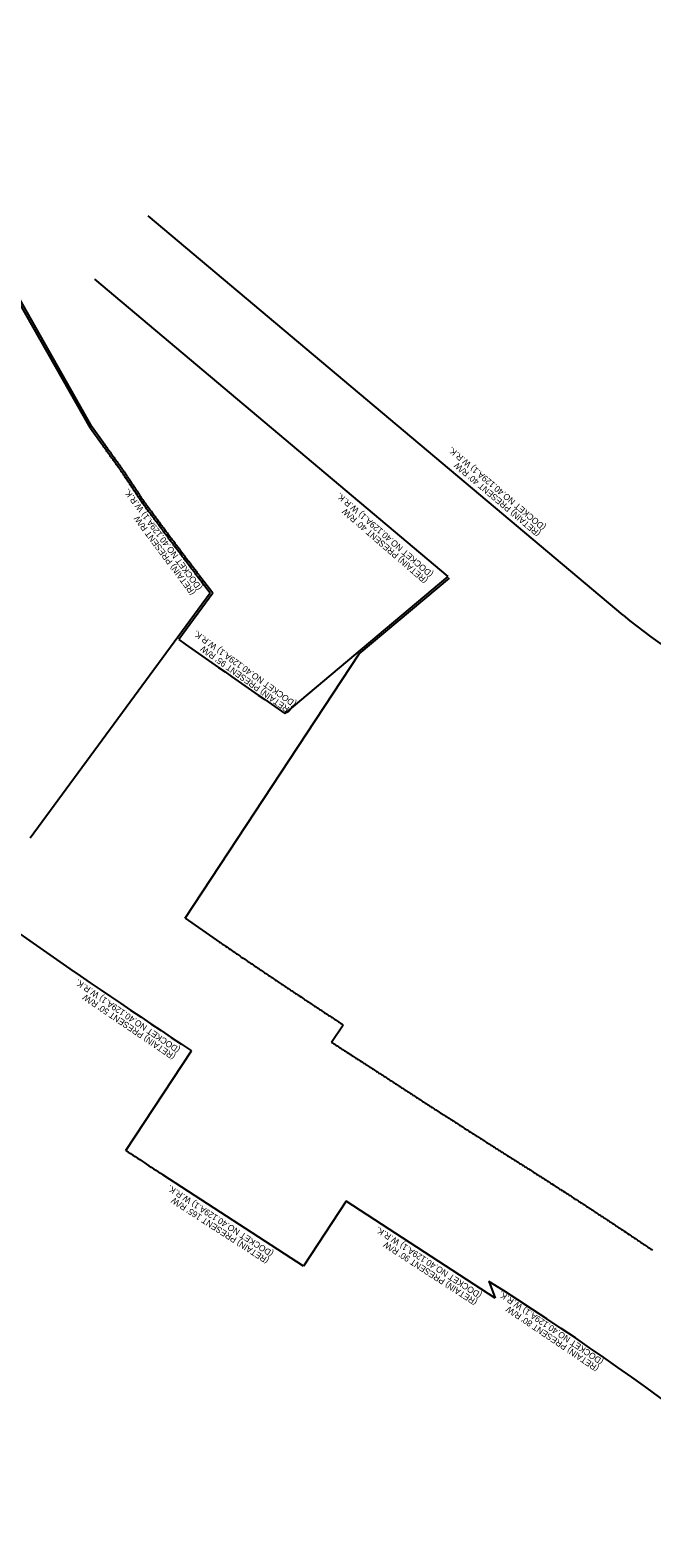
# Model space of a CAD drawing. Extents: x 2004008 to 2024436, y 806921 to 864820.
# Drawn here: x 2021261 to 2021860, y 814347 to 815799 of the extents above; entities that cross this region are included whole.
import ezdxf

# ---------------------------------------------------------------- set-up
doc = ezdxf.new("R2010")
doc.units = 0
for name, color, linetype in [('RD_PD_DR_ErosCtrl', 7, 'Continuous'), ('RD_PD_Final_LnLine', 7, 'Continuous'), ('RD_PD_MedBWall', 7, 'Continuous')]:
    doc.layers.add(name, color=color, linetype=linetype)

msp = doc.modelspace()

# ---------------------------------------------------------------- linework, layer by layer
at = {"layer": 'RD_PD_Final_LnLine'}
for p, q in [((2021832.3, 815235.7), (2021374.9, 815620.3)), ((2021663.8, 815272.9), (2021323.4, 815559.1)), ((2021506.7, 815141.1), (2021663.8, 815272.9)), ((2021437, 815257), (2021404.3, 815212.4)), ((2021353.4, 814720.1), (2021416.7, 814816.1)), ((2021524.6, 814608.7), (2021388.9, 814696.9)), ((2021565.5, 814671.5), (2021524.6, 814608.7)), ((2021709.1, 814578.1), (2021565.5, 814671.5)), ((2021703.1, 814594.2), (2021709.1, 814578.1))]:
    msp.add_line(p, q, dxfattribs=at)
for points in [[(2021321, 815416.6), (2021245.8, 815549.5), (2021197.2, 815663), (2021170, 815798.8)], [(2021437, 815257), (2021428.6, 815268), (2021428.1, 815268.7), (2021427.5, 815269.5), (2021426.8, 815270.4), (2021426.3, 815271.1), (2021425.7, 815271.9), (2021425.1, 815272.7), (2021424.5, 815273.5), (2021423.4, 815274.8), (2021423.3, 815275), (2021423.2, 815275.2), (2021422.5, 815276.1), (2021421.9, 815276.9), (2021421.3, 815277.6), (2021420.7, 815278.5), (2021420.1, 815279.3), (2021419.5, 815280.1), (2021418.9, 815280.9), (2021418.3, 815281.6), (2021417.7, 815282.5), (2021417, 815283.3), (2021416.5, 815284), (2021415.9, 815284.8), (2021415.2, 815285.7), (2021414.7, 815286.4), (2021414.1, 815287.2), (2021413.4, 815288.1), (2021412.8, 815288.8), (2021412.3, 815289.6), (2021411.6, 815290.4), (2021411, 815291.2), (2021410.4, 815292), (2021409.8, 815292.8), (2021409.3, 815293.5), (2021408.6, 815294.4), (2021408, 815295.2), (2021407.5, 815295.9), (2021406.8, 815296.8), (2021406.2, 815297.6), (2021405.6, 815298.3), (2021405, 815299.2), (2021404.4, 815300), (2021403.8, 815300.8), (2021403.2, 815301.6), (2021402.6, 815302.3), (2021402, 815303.2), (2021401.3, 815304.1), (2021400.8, 815304.7), (2021400.2, 815305.5), (2021399.5, 815306.5), (2021399, 815307.2), (2021398.4, 815307.9), (2021397.7, 815308.8), (2021397.2, 815309.6), (2021396.5, 815310.4), (2021396, 815311.1), (2021395.4, 815311.9), (2021394.6, 815312.9), (2021394.1, 815313.6), (2021393.5, 815314.5), (2021392.9, 815315.3), (2021392.3, 815316), (2021391.7, 815316.9), (2021391.1, 815317.7), (2021390.5, 815318.4), (2021389.9, 815319.3), (2021389.3, 815320.1), (2021388.7, 815320.9), (2021388.1, 815321.7), (2021387.5, 815322.5), (2021387, 815323.3), (2021386.3, 815324.1), (2021385.8, 815324.9), (2021385.2, 815325.7), (2021384.5, 815326.5), (2021383.9, 815327.4), (2021383.4, 815328.1), (2021382.7, 815329), (2021382.1, 815329.8), (2021381.5, 815330.6), (2021381, 815331.4), (2021380.4, 815332.1), (2021379.8, 815333), (2021379.2, 815333.8), (2021378.6, 815334.5), (2021378, 815335.4), (2021377.4, 815336.2), (2021376.9, 815336.8), (2021376.2, 815337.8), (2021375.6, 815338.6), (2021375, 815339.3), (2021374.4, 815340.2), (2021373.8, 815341), (2021373.3, 815341.7), (2021372.6, 815342.6), (2021372, 815343.5), (2021371.4, 815344.3), (2021370.4, 815345.8), (2021369.8, 815346.7), (2021369.2, 815347.5), (2021368.7, 815348.3), (2021368.2, 815349.1), (2021367.6, 815349.9), (2021367, 815350.8), (2021366.5, 815351.7), (2021366, 815352.4), (2021365.4, 815353.3), (2021364.8, 815354.1), (2021364.2, 815355), (2021363.7, 815355.8), (2021363.2, 815356.6), (2021362.6, 815357.4), (2021362.1, 815358.2), (2021361.5, 815359.1), (2021360.9, 815360), (2021360.4, 815360.8), (2021359.9, 815361.6), (2021359.3, 815362.4), (2021358.7, 815363.2), (2021358.1, 815364.1), (2021357.6, 815365), (2021357.1, 815365.7), (2021356.5, 815366.6), (2021356, 815367.4), (2021355.4, 815368.2), (2021354.8, 815369.1), (2021354.3, 815370), (2021353.7, 815370.7), (2021353.2, 815371.6), (2021352.6, 815372.4), (2021352, 815373.3), (2021351.5, 815374.1), (2021351, 815374.9), (2021350.4, 815375.7), (2021349.9, 815376.4), (2021349.7, 815376.8), (2021349.1, 815377.6), (2021348.6, 815378.3), (2021347.9, 815379.2), (2021347.3, 815380), (2021346.7, 815380.8), (2021346.2, 815381.6), (2021345.6, 815382.5), (2021345, 815383.3), (2021344.4, 815384.1), (2021343.8, 815384.9), (2021343.2, 815385.7), (2021342.6, 815386.6), (2021342, 815387.4), (2021341.5, 815388.1), (2021341, 815388.8), (2021340.3, 815389.8), (2021339.7, 815390.6), (2021339.1, 815391.4), (2021338.6, 815392.2), (2021338, 815393), (2021337.4, 815393.8), (2021336.8, 815394.6), (2021336.2, 815395.4), (2021335.6, 815396.2), (2021335, 815397), (2021334.4, 815397.9), (2021333.8, 815398.7), (2021333.4, 815399.4), (2021332.7, 815400.3), (2021332.1, 815401.1), (2021331.5, 815401.9), (2021321, 815416.6)]]:
    msp.add_lwpolyline(points, dxfattribs=at)
for centre, radius, start, end in [((2022154.1, 815618.5), 500, 229.9463, 260.9553), ((2025178.7, 820524), 6516.1, 234.60258, 235.69919), ((2025178.7, 820524), 6836.1, 233.4539, 236.61156), ((2025178.7, 820524), 6951.1, 236.61156, 236.96135), ((2020043.9, 811970), 3104.7, 47.9016, 57.6957)]:
    msp.add_arc(centre, radius, start, end, dxfattribs=at)
at = {"layer": 'RD_PD_MedBWall'}
for p, q in [((2021578.2, 815198.5), (2021665.1, 815271.4)), ((2021434.5, 815256.9), (2021261.2, 815020.8)), ((2021410.5, 814943.8), (2021578.2, 815198.5)), ((2021551.6, 814824.4), (2021562.6, 814841.1))]:
    msp.add_line(p, q, dxfattribs=at)
for points in [[(2021319.3, 815415.6), (2021244, 815548.6), (2021195.2, 815662.4), (2021167.9, 815799)], [(2021434.5, 815256.9), (2021427, 815266.8), (2021426.5, 815267.5), (2021425.9, 815268.3), (2021425.2, 815269.2), (2021424.7, 815269.9), (2021424.1, 815270.7), (2021423.5, 815271.5), (2021422.9, 815272.3), (2021421.8, 815273.6), (2021421.7, 815273.8), (2021421.6, 815274), (2021420.9, 815274.9), (2021420.3, 815275.7), (2021419.7, 815276.4), (2021419.1, 815277.3), (2021418.5, 815278.1), (2021417.9, 815278.9), (2021417.3, 815279.7), (2021416.7, 815280.4), (2021416.1, 815281.2), (2021415.4, 815282.1), (2021414.9, 815282.8), (2021414.3, 815283.6), (2021413.6, 815284.5), (2021413.1, 815285.2), (2021412.5, 815286), (2021411.8, 815286.9), (2021411.2, 815287.6), (2021410.7, 815288.4), (2021410, 815289.2), (2021409.4, 815290), (2021408.8, 815290.8), (2021408.2, 815291.6), (2021407.7, 815292.3), (2021407, 815293.2), (2021406.4, 815294), (2021405.9, 815294.7), (2021405.2, 815295.6), (2021404.6, 815296.4), (2021404.1, 815297.1), (2021403.4, 815298), (2021402.8, 815298.8), (2021402.2, 815299.6), (2021401.6, 815300.4), (2021401, 815301.1), (2021400.4, 815302), (2021399.7, 815302.9), (2021399.2, 815303.5), (2021398.6, 815304.3), (2021397.9, 815305.3), (2021397.4, 815306), (2021396.8, 815306.7), (2021396.1, 815307.6), (2021395.6, 815308.4), (2021394.9, 815309.2), (2021394.4, 815309.9), (2021393.8, 815310.7), (2021393, 815311.7), (2021392.5, 815312.4), (2021391.8, 815313.3), (2021391.2, 815314.1), (2021390.7, 815314.8), (2021390.1, 815315.7), (2021389.5, 815316.5), (2021388.9, 815317.3), (2021388.3, 815318.1), (2021387.7, 815318.9), (2021387.1, 815319.7), (2021386.5, 815320.5), (2021385.9, 815321.3), (2021385.4, 815322.1), (2021384.7, 815322.9), (2021384.2, 815323.7), (2021383.6, 815324.5), (2021382.9, 815325.4), (2021382.3, 815326.2), (2021381.8, 815326.9), (2021381.1, 815327.8), (2021380.5, 815328.6), (2021379.9, 815329.4), (2021379.3, 815330.2), (2021378.8, 815330.9), (2021378.2, 815331.8), (2021377.6, 815332.6), (2021377, 815333.3), (2021376.4, 815334.2), (2021375.8, 815335), (2021375.3, 815335.6), (2021374.6, 815336.6), (2021374, 815337.4), (2021373.4, 815338.1), (2021372.8, 815339), (2021372.2, 815339.8), (2021371.7, 815340.6), (2021371, 815341.4), (2021370.4, 815342.3), (2021369.8, 815343.1), (2021368.7, 815344.7), (2021368.1, 815345.6), (2021367.6, 815346.4), (2021367.1, 815347.2), (2021366.5, 815348), (2021366, 815348.8), (2021365.3, 815349.7), (2021364.8, 815350.6), (2021364.3, 815351.3), (2021363.7, 815352.1), (2021363.2, 815353), (2021362.6, 815353.9), (2021362, 815354.7), (2021361.5, 815355.5), (2021361, 815356.3), (2021360.4, 815357.1), (2021359.8, 815358), (2021359.2, 815358.9), (2021358.7, 815359.7), (2021358.2, 815360.5), (2021357.6, 815361.3), (2021357.1, 815362.1), (2021356.5, 815363), (2021355.9, 815363.9), (2021355.4, 815364.6), (2021354.9, 815365.5), (2021354.3, 815366.3), (2021353.7, 815367.1), (2021353.1, 815368), (2021352.6, 815368.9), (2021352.1, 815369.6), (2021351.5, 815370.4), (2021351, 815371.3), (2021350.4, 815372.2), (2021349.8, 815373), (2021349.3, 815373.8), (2021348.7, 815374.6), (2021348.3, 815375.3), (2021348.1, 815375.6), (2021347.5, 815376.4), (2021347, 815377.1), (2021346.3, 815378), (2021345.7, 815378.9), (2021345.1, 815379.7), (2021344.5, 815380.5), (2021344, 815381.3), (2021343.4, 815382.1), (2021342.8, 815382.9), (2021342.2, 815383.7), (2021341.6, 815384.5), (2021341, 815385.4), (2021340.4, 815386.2), (2021339.9, 815387), (2021339.4, 815387.7), (2021338.7, 815388.6), (2021338.1, 815389.4), (2021337.5, 815390.2), (2021336.9, 815391), (2021336.3, 815391.8), (2021335.8, 815392.6), (2021335.2, 815393.4), (2021334.6, 815394.3), (2021334, 815395.1), (2021333.4, 815395.9), (2021332.8, 815396.8), (2021332.2, 815397.6), (2021331.7, 815398.2), (2021331.1, 815399.1), (2021330.5, 815399.9), (2021329.9, 815400.7), (2021319.4, 815415.4)], [(2021410.5, 814943.8), (2021443.6, 814920.8), (2021444.2, 814920.4), (2021445.1, 814919.8), (2021445.9, 814919.2), (2021446.8, 814918.6), (2021447.6, 814918.1), (2021448.4, 814917.5), (2021449.2, 814917), (2021450.9, 814915.9), (2021451.9, 814915.2), (2021452.6, 814914.7), (2021454.2, 814913.6), (2021455, 814913.1), (2021455.9, 814912.5), (2021456.7, 814911.9), (2021457.5, 814911.4), (2021458.3, 814910.8), (2021459.1, 814910.3), (2021460.1, 814909.6), (2021460.8, 814909.1), (2021461.2, 814908.8), (2021462.2, 814908.2), (2021463, 814907.7), (2021463.8, 814907.1), (2021464.6, 814906.5), (2021466.4, 814905.4), (2021467.2, 814904.8), (2021467.9, 814904.3), (2021468.8, 814903.7), (2021469.6, 814903.2), (2021470.4, 814902.6), (2021471.3, 814902), (2021472.2, 814901.4), (2021472.9, 814900.9), (2021473.7, 814900.4), (2021474.6, 814899.8), (2021476.3, 814898.6), (2021477.1, 814898.1), (2021478, 814897.5), (2021478.8, 814896.9), (2021479.5, 814896.5), (2021480.4, 814895.9), (2021481.3, 814895.3), (2021482.1, 814894.7), (2021482.8, 814894.2), (2021483.7, 814893.7), (2021484.5, 814893.1), (2021485.3, 814892.5), (2021486.3, 814891.9), (2021487, 814891.4), (2021487.4, 814891.1), (2021488.3, 814890.5), (2021489.1, 814890), (2021490, 814889.4), (2021490.9, 814888.8), (2021491.6, 814888.3), (2021492.5, 814887.8), (2021493.3, 814887.2), (2021494, 814886.7), (2021495, 814886.1), (2021495.8, 814885.5), (2021496.6, 814885), (2021497.6, 814884.3), (2021498.3, 814883.9), (2021499.1, 814883.3), (2021500.1, 814882.6), (2021500.8, 814882.2), (2021501.5, 814881.7), (2021502.3, 814881.1), (2021503.3, 814880.5), (2021504.2, 814879.9), (2021504.9, 814879.4), (2021505.8, 814878.9), (2021506.7, 814878.2), (2021507.4, 814877.7), (2021508.2, 814877.2), (2021509.1, 814876.6), (2021509.8, 814876.1), (2021510.8, 814875.5), (2021511.6, 814875), (2021512.4, 814874.4), (2021513.2, 814873.8), (2021514.1, 814873.3), (2021515, 814872.6), (2021515.7, 814872.2), (2021516.6, 814871.6), (2021516.9, 814871.4), (2021517.5, 814871), (2021518.4, 814870.4), (2021519.2, 814869.9), (2021520, 814869.3), (2021520.9, 814868.7), (2021522.4, 814867.7), (2021523.4, 814867.1), (2021524.3, 814866.5), (2021525, 814866), (2021525.9, 814865.4), (2021526.7, 814864.9), (2021527.5, 814864.4), (2021528.4, 814863.8), (2021529.2, 814863.2), (2021530, 814862.7), (2021530.9, 814862.1), (2021531.7, 814861.6), (2021532.5, 814861), (2021533.2, 814860.5), (2021534.2, 814859.9), (2021535.1, 814859.3), (2021535.7, 814858.9), (2021536.7, 814858.2), (2021537.6, 814857.6), (2021538.3, 814857.2), (2021539.2, 814856.6), (2021540, 814856), (2021540.8, 814855.5), (2021541.7, 814854.9), (2021542.5, 814854.4), (2021543.3, 814853.8), (2021544.4, 814853.2), (2021544.8, 814852.9), (2021545.4, 814852.5), (2021546.2, 814851.9), (2021547.1, 814851.4), (2021547.9, 814850.8), (2021548.7, 814850.3), (2021549.6, 814849.7), (2021550.6, 814849.1), (2021551.5, 814848.5), (2021552.1, 814848.1), (2021552.9, 814847.5), (2021553.7, 814847), (2021554.6, 814846.4), (2021555.4, 814845.9), (2021556.3, 814845.3), (2021557.3, 814844.6), (2021558.1, 814844.1), (2021558.8, 814843.6), (2021559.6, 814843.1), (2021560.4, 814842.5), (2021561.3, 814842), (2021562.1, 814841.4), (2021562.6, 814841.1)], [(2021551.6, 814824.4), (2021552, 814824.2), (2021552.8, 814823.6), (2021553.7, 814823), (2021554.5, 814822.5), (2021555.3, 814822), (2021556.1, 814821.4), (2021556.9, 814820.9), (2021557.8, 814820.3), (2021558.6, 814819.8), (2021559.5, 814819.2), (2021560.3, 814818.6), (2021561.1, 814818.2), (2021561.4, 814817.9), (2021562.3, 814817.4), (2021563, 814816.9), (2021563.9, 814816.3), (2021564.8, 814815.7), (2021565.6, 814815.2), (2021566.4, 814814.7), (2021568.1, 814813.6), (2021569, 814813), (2021569.8, 814812.5), (2021571.5, 814811.4), (2021572.3, 814810.9), (2021573.1, 814810.4), (2021574, 814809.8), (2021574.9, 814809.2), (2021575.7, 814808.7), (2021576.5, 814808.2), (2021577.3, 814807.7), (2021578.2, 814807.1), (2021579.1, 814806.5), (2021580.7, 814805.4), (2021581.6, 814804.9), (2021582.4, 814804.4), (2021583.2, 814803.9), (2021584.1, 814803.3), (2021584.9, 814802.7), (2021585.7, 814802.2), (2021586.6, 814801.7), (2021587.5, 814801.1), (2021588.3, 814800.5), (2021589.1, 814800.1), (2021589.9, 814799.5), (2021590.8, 814798.9), (2021591.7, 814798.4), (2021592.4, 814797.9), (2021593, 814797.5), (2021593.9, 814796.9), (2021594.7, 814796.4), (2021595.5, 814795.9), (2021596.4, 814795.3), (2021597.2, 814794.8), (2021598.1, 814794.2), (2021599, 814793.7), (2021599.8, 814793.1), (2021600.6, 814792.6), (2021601.4, 814792), (2021602.3, 814791.5), (2021603.1, 814791), (2021604, 814790.4), (2021604.8, 814789.8), (2021605.6, 814789.3), (2021606.4, 814788.8), (2021607.3, 814788.2), (2021608.1, 814787.7), (2021608.9, 814787.2), (2021609.9, 814786.6), (2021610.7, 814786), (2021611.5, 814785.5), (2021612.3, 814785), (2021613.2, 814784.4), (2021614, 814783.9), (2021614.8, 814783.3), (2021615.7, 814782.8), (2021616.6, 814782.2), (2021617.3, 814781.7), (2021618.2, 814781.2), (2021619, 814780.6), (2021619.9, 814780.1), (2021620.8, 814779.5), (2021621.6, 814778.9), (2021622.4, 814778.4), (2021623.2, 814777.9), (2021624.1, 814777.3), (2021624.9, 814776.8), (2021625.7, 814776.2), (2021626.6, 814775.7), (2021627.5, 814775.1), (2021628.2, 814774.6), (2021629.1, 814774.1), (2021629.9, 814773.5), (2021630.8, 814773), (2021631.6, 814772.4), (2021632.5, 814771.9), (2021633.3, 814771.3), (2021634.1, 814770.8), (2021635, 814770.3), (2021635.8, 814769.7), (2021636.6, 814769.2), (2021637.5, 814768.6), (2021638.4, 814768), (2021639.2, 814767.5), (2021640, 814767), (2021640.8, 814766.4), (2021641.7, 814765.9), (2021642.5, 814765.4), (2021643.4, 814764.8), (2021644.2, 814764.2), (2021645, 814763.7), (2021645.8, 814763.2), (2021646.1, 814763), (2021646.9, 814762.5), (2021647.7, 814762), (2021648.5, 814761.5), (2021649.4, 814760.9), (2021650.3, 814760.3), (2021651.1, 814759.8), (2021651.9, 814759.3), (2021652.8, 814758.8), (2021655.3, 814757.1), (2021656.1, 814756.6), (2021656.9, 814756.1), (2021657.9, 814755.5), (2021658.7, 814755), (2021659.5, 814754.4), (2021660.3, 814753.9), (2021661.2, 814753.3), (2021662.1, 814752.8), (2021662.9, 814752.3), (2021663.7, 814751.7), (2021664.5, 814751.2), (2021665.4, 814750.6), (2021666.3, 814750.1), (2021667.1, 814749.6), (2021667.9, 814749), (2021668.7, 814748.6), (2021669.6, 814748), (2021671.3, 814746.9), (2021672.1, 814746.4), (2021673, 814745.8), (2021673.9, 814745.2), (2021674.7, 814744.7), (2021675.4, 814744.2), (2021676.2, 814743.7), (2021677.1, 814743.2), (2021678, 814742.6), (2021678.8, 814742.1), (2021679.7, 814741.5), (2021680.5, 814741), (2021681.3, 814740.5), (2021682.1, 814740), (2021683, 814739.4), (2021683.9, 814738.8), (2021685.5, 814737.8), (2021686.4, 814737.2), (2021687.2, 814736.7), (2021688.1, 814736.2), (2021688.9, 814735.6), (2021689.8, 814735.1), (2021690.7, 814734.5), (2021691.5, 814734), (2021692.2, 814733.5), (2021693.1, 814733), (2021694, 814732.4), (2021694.9, 814731.8), (2021695.7, 814731.3), (2021696.5, 814730.8), (2021697.4, 814730.2), (2021698.2, 814729.7), (2021699, 814729.2), (2021699.9, 814728.6), (2021700.8, 814728), (2021701.6, 814727.5), (2021702.4, 814727), (2021703.2, 814726.5), (2021704.1, 814725.9), (2021704.9, 814725.4), (2021705.7, 814724.9), (2021706.5, 814724.4), (2021707.4, 814723.8), (2021708.2, 814723.3), (2021709.1, 814722.8), (2021709.9, 814722.2), (2021710.8, 814721.7), (2021711.6, 814721.2), (2021712.4, 814720.6), (2021713.3, 814720.1), (2021714.1, 814719.6), (2021715, 814719), (2021715.8, 814718.5), (2021716.7, 814717.9), (2021717.5, 814717.4), (2021718.4, 814716.9), (2021719.2, 814716.3), (2021720.1, 814715.8), (2021720.9, 814715.2), (2021721.7, 814714.7), (2021722.6, 814714.2), (2021723.4, 814713.7), (2021724.3, 814713.1), (2021725.1, 814712.6), (2021726, 814712.1), (2021726.8, 814711.5), (2021727.7, 814711), (2021728.5, 814710.5), (2021729.3, 814709.9), (2021730.2, 814709.4), (2021731, 814708.9), (2021731.9, 814708.3), (2021732.7, 814707.8), (2021733.6, 814707.2), (2021734.4, 814706.7), (2021735.3, 814706.2), (2021736.1, 814705.6), (2021736.9, 814705.1), (2021737.8, 814704.6), (2021738.6, 814704), (2021739.5, 814703.5), (2021740.3, 814703), (2021741.2, 814702.4), (2021742.1, 814701.9), (2021742.9, 814701.4), (2021743.7, 814700.8), (2021744.2, 814700.5), (2021745.1, 814699.9), (2021746.8, 814698.8), (2021747.7, 814698.3), (2021749.4, 814697.2), (2021750.3, 814696.6), (2021751, 814696.1), (2021751.8, 814695.6), (2021752.7, 814695), (2021753.6, 814694.5), (2021754.4, 814694), (2021755.2, 814693.4), (2021756.9, 814692.3), (2021757.7, 814691.8), (2021758.6, 814691.3), (2021759.4, 814690.7), (2021760.3, 814690.2), (2021761.2, 814689.6), (2021762, 814689), (2021762.8, 814688.5), (2021763.6, 814688), (2021765.3, 814687), (2021766.1, 814686.4), (2021767, 814685.8), (2021767.9, 814685.3), (2021768.7, 814684.8), (2021769.5, 814684.2), (2021770.4, 814683.7), (2021771.2, 814683.1), (2021772, 814682.6), (2021772.9, 814682), (2021773.8, 814681.5), (2021774.6, 814681), (2021776.3, 814679.9), (2021777.9, 814678.8), (2021778.8, 814678.3), (2021779.6, 814677.8), (2021780.4, 814677.2), (2021781.3, 814676.7), (2021782.2, 814676.1), (2021783, 814675.6), (2021784.7, 814674.4), (2021785.6, 814673.9), (2021786.3, 814673.4), (2021787.2, 814672.9), (2021788, 814672.3), (2021788.9, 814671.8), (2021789.7, 814671.2), (2021790.6, 814670.7), (2021791.4, 814670.2), (2021792, 814669.8), (2021792.9, 814669.2), (2021793.8, 814668.6), (2021794.6, 814668.1), (2021795.4, 814667.5), (2021796.3, 814667), (2021797.1, 814666.4), (2021798, 814665.9), (2021798.8, 814665.3), (2021799.6, 814664.8), (2021800.5, 814664.2), (2021801.3, 814663.7), (2021802.1, 814663.1), (2021803, 814662.6), (2021803.8, 814662), (2021804.6, 814661.5), (2021805.5, 814660.9), (2021806.3, 814660.4), (2021807.1, 814659.8), (2021808, 814659.3), (2021808.8, 814658.7), (2021809.6, 814658.2), (2021810.5, 814657.6), (2021811.3, 814657.1), (2021812.2, 814656.5), (2021813, 814656), (2021813.8, 814655.4), (2021814.7, 814654.9), (2021815.5, 814654.3), (2021816.3, 814653.8), (2021817.2, 814653.2), (2021817.9, 814652.7), (2021818.8, 814652.2), (2021819.7, 814651.6), (2021820.5, 814651.1), (2021821.3, 814650.5), (2021822.2, 814649.9), (2021823, 814649.4), (2021823.8, 814648.8), (2021824.7, 814648.3), (2021825.5, 814647.7), (2021826.4, 814647.2), (2021827.1, 814646.7), (2021827.3, 814646.5), (2021828.3, 814645.8), (2021829.1, 814645.3), (2021829.9, 814644.8), (2021830.8, 814644.2), (2021831.6, 814643.7), (2021832.4, 814643.1), (2021833.3, 814642.5), (2021834.9, 814641.4), (2021835.7, 814640.9), (2021836.6, 814640.3), (2021838.2, 814639.2), (2021839.1, 814638.7), (2021840, 814638), (2021840.7, 814637.5), (2021841.6, 814637), (2021842.5, 814636.4), (2021843.3, 814635.8), (2021844, 814635.3), (2021844.9, 814634.8), (2021845.8, 814634.1), (2021846.6, 814633.6), (2021847.4, 814633.1), (2021848.2, 814632.5), (2021849.1, 814631.9), (2021849.9, 814631.4), (2021850.7, 814630.8), (2021851.5, 814630.3), (2021852.4, 814629.7), (2021853.2, 814629.2), (2021854, 814628.6), (2021854.9, 814628.1), (2021855.7, 814627.5), (2021856.5, 814626.9), (2021857.3, 814626.4), (2021858.2, 814625.8), (2021859.1, 814625.2), (2021859.8, 814624.7), (2021860.7, 814624.2)]]:
    msp.add_lwpolyline(points, dxfattribs=at)

# ---------------------------------------------------------------- texts
at = {"layer": 'RD_PD_DR_ErosCtrl'}
for s, rotation, p in [('(DOCKET NO.40.129A.1) W.R.K.', 139.8622, (2021758.4, 815321.3)), ("(RETAIN) PRESENT 40' R/W", 139.8622, (2021753.3, 815315.3)), ('(DOCKET NO.40.129A.1) W.R.K.', 126.7256, (2021427.2, 815262.4)), ('(DOCKET NO.40.129A.1) W.R.K.', 139.2288, (2021649.9, 815276.1)), ('(RETAIN) PRESENT R/W', 126.7256, (2021420.9, 815257.7)), ("(RETAIN) PRESENT 40' R/W", 139.2288, (2021644.7, 815270.1)), ('(DOCKET NO.40.129A.1) W.R.K.', 144.2608, (2021518.1, 815151.6)), ("(RETAIN) PRESENT 95' R/W", 144.2608, (2021513.5, 815145.1)), ('(DOCKET NO.40.129A.1) W.R.K.', 145.8529, (2021406.1, 814818.5)), ("(RETAIN) PRESENT 50' R/W", 145.8529, (2021401.7, 814812)), ('(DOCKET NO.40.129A.1) W.R.K.', 147.1126, (2021496.1, 814622.4)), ("(RETAIN) PRESENT 165' R/W", 147.1126, (2021491.8, 814615.7)), ('(DOCKET NO.40.129A.1) W.R.K.', 147.1126, (2021696.8, 814582.3)), ("(RETAIN) PRESENT 90' R/W", 147.1126, (2021692.5, 814575.6)), ('(DOCKET NO.40.129A.1) W.R.K.', 146.0049, (2021814, 814518.4)), ("(RETAIN) PRESENT 80' R/W", 146.0049, (2021809.6, 814511.8))]:
    msp.add_text(s, height=6, rotation=rotation, dxfattribs=at).set_placement(p)

doc.saveas('drawing.dxf')
